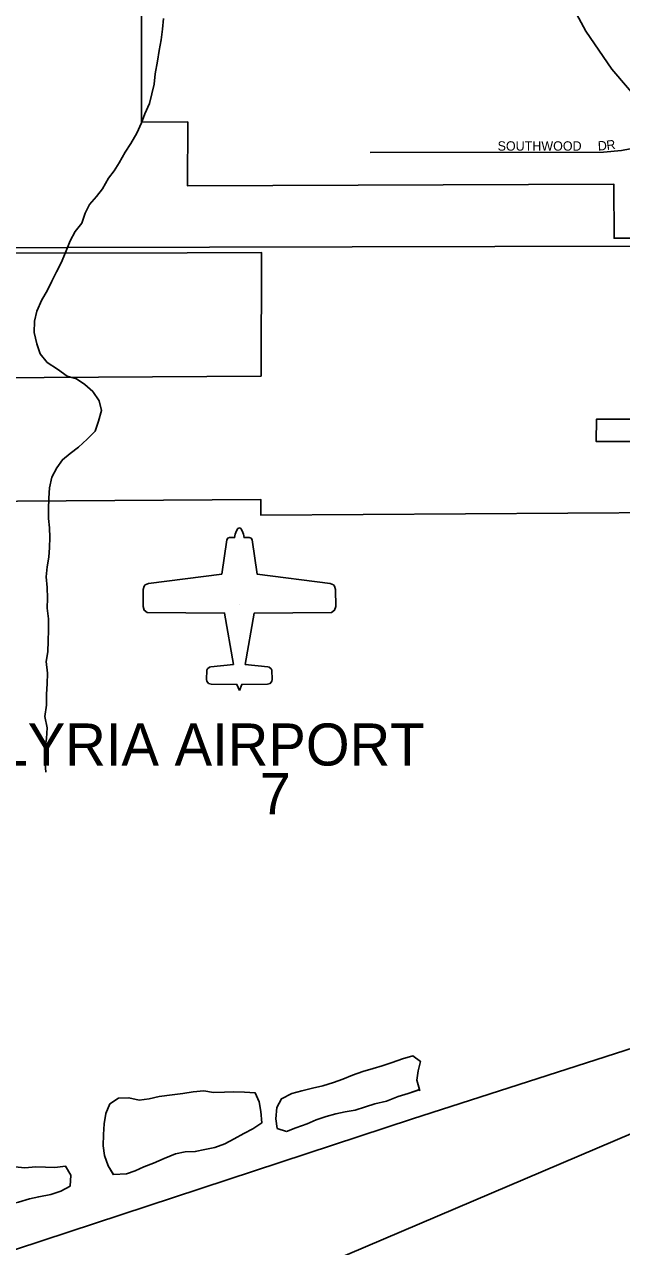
# Model space of a CAD drawing. Extents: x 1857828 to 2277390, y 930619 to 1324581.
# Drawn here: x 2077646 to 2080841, y 1210395 to 1216929 of the extents above; entities that cross this region are included whole.
import ezdxf

# ---------------------------------------------------------------- set-up
doc = ezdxf.new("R2010")
doc.units = 0
for name, color, linetype in [('GM_X_Airport_Class_3', 7, 'Continuous'), ('GM_X_Airport_Location_Class_3', 7, 'Continuous'), ('GM_X_Airport_Text_Class_3', 7, 'Continuous'), ('GM_X_Corporation', 7, 'Continuous'), ('GM_X_County_Road', 7, 'Continuous'), ('GM_X_Minor_Lake', 7, 'Continuous'), ('GM_X_Minor_River', 7, 'Continuous'), ('GM_X_Section', 7, 'Continuous'), ('GM_X_Section_Text', 7, 'Continuous'), ('GM_X_Township_Subdivision', 7, 'Continuous'), ('GM_X_Township_Subdivision_Text', 7, 'Continuous'), ('GM_X_US_Route', 7, 'Continuous')]:
    doc.layers.add(name, color=color, linetype=linetype)

msp = doc.modelspace()

# ---------------------------------------------------------------- linework, layer by layer
at = {"layer": 'GM_X_Airport_Class_3'}
for points in [[(2078795.9, 1214237.5), (2078788.2, 1214234.2), (2078780, 1214222.1), (2078774, 1214204), (2078770.7, 1214185.7), (2078743.9, 1214185.8), (2078733.5, 1214182.2), (2078728, 1214174.3), (2078701.5, 1213990.2), (2078309.8, 1213940.1), (2078292.6, 1213932.5), (2078286.3, 1213925.4), (2078280.9, 1213907.3), (2078280.6, 1213816.5), (2078286.9, 1213797), (2078303.5, 1213784.9), (2078716.4, 1213782.2), (2078764.4, 1213507.8), (2078642.9, 1213494.1), (2078636, 1213492.2), (2078625, 1213483.1), (2078621.9, 1213476.6), (2078620.7, 1213426.2), (2078621.9, 1213418.5), (2078630.9, 1213406.1), (2078645.5, 1213401.3), (2078783.1, 1213400.9), (2078795.9, 1213368.8)], [(2078795.9, 1213368.8), (2078808.7, 1213400.9), (2078946.3, 1213401.3), (2078960.9, 1213406.1), (2078969.9, 1213418.5), (2078971.1, 1213426.2), (2078969.9, 1213476.6), (2078966.8, 1213483.1), (2078955.8, 1213492.2), (2078948.9, 1213494.1), (2078827.4, 1213507.8), (2078875.4, 1213782.2), (2079288.3, 1213784.9), (2079304.9, 1213797), (2079311.2, 1213816.5), (2079310.9, 1213907.3), (2079305.5, 1213925.4), (2079299.2, 1213932.5), (2079282, 1213940.1), (2078890.3, 1213990.2), (2078863.8, 1214174.3), (2078858.3, 1214182.2), (2078848, 1214185.8), (2078821.1, 1214185.7), (2078817.8, 1214204), (2078811.8, 1214222.1), (2078803.6, 1214234.2), (2078795.9, 1214237.5)]]:
    msp.add_lwpolyline(points, dxfattribs=at)
at = {"layer": 'GM_X_Airport_Location_Class_3'}
msp.add_line((2078795.9, 1213827.2), (2078795.9, 1213827.2), dxfattribs=at)
at = {"layer": 'GM_X_Corporation'}
for points in [[(2078272.2, 1217857.5), (2078272.2, 1216406.7), (2078519.9, 1216407.6), (2078518, 1216066.1), (2080799.4, 1216074.4), (2080801.1, 1215785.4), (2081069.2, 1215786.8)], [(2076298.8, 1215032.7), (2078912.2, 1215049.3), (2078913.5, 1215709.7), (2078516, 1215707.1), (2075296.1, 1215705)], [(2081058.7, 1214818.7), (2080706.5, 1214817.7), (2080705.1, 1214698.5), (2081053.7, 1214699.4)], [(2081100.6, 1214319.6), (2078910.7, 1214305.6), (2078910.9, 1214388.9), (2076565.7, 1214373.3)]]:
    msp.add_lwpolyline(points, dxfattribs=at)
at = {"layer": 'GM_X_County_Road'}
for points in [[(2084481.4, 1213642.1), (2084249.4, 1213874.3), (2084213, 1213908.4), (2084181.9, 1213938), (2084150, 1213963.7), (2084103.8, 1213997.9), (2084049, 1214032.5), (2083824.5, 1214148.2), (2082699.2, 1214730.9), (2082586.9, 1214795.9), (2082546.1, 1214823.7), (2082500.7, 1214856.2), (2082438.5, 1214905.4), (2082371.7, 1214977.8), (2082055.3, 1215322), (2081693.4, 1215722.8), (2081081.5, 1216369.5), (2080916.1, 1216542.2), (2080871.6, 1216592.1), (2080789.2, 1216690.2), (2080649.8, 1216892.8), (2080547.6, 1217082.7)], [(2073594.6, 1207932.1), (2076220, 1209011.3), (2080999.8, 1211044.3), (2081275, 1211117.7), (2081474.9, 1211179.1), (2082358.5, 1211451.5), (2082456.5, 1211486.3), (2082532.4, 1211514.8), (2082604.4, 1211541.4), (2082696.3, 1211576.1), (2082794.2, 1211618.8), (2082898, 1211665.6), (2082987.9, 1211714.3), (2083091.7, 1211771.2), (2083161.6, 1211809.7), (2083191.6, 1211824), (2083235.5, 1211842.3), (2083439.5, 1211899.7), (2084071.3, 1212080.3), (2085602.9, 1212500.2)]]:
    msp.add_lwpolyline(points, dxfattribs=at)
at = {"layer": 'GM_X_Minor_Lake'}
for points in [[(2079759.4, 1211234.2), (2079744.8, 1211284.2), (2079752.6, 1211334.5), (2079764.3, 1211384.8), (2079724.1, 1211414.7), (2079668, 1211398.3), (2079613.9, 1211379.9), (2079559.9, 1211361.5), (2079511.8, 1211347.1), (2079455.8, 1211330.7), (2079401.7, 1211312.3), (2079349.7, 1211289.9), (2079299.7, 1211271.5), (2079241.6, 1211255), (2079187.5, 1211242.7), (2079129.4, 1211228.2), (2079077.4, 1211213.9), (2079021.4, 1211185.4), (2078995.5, 1211139), (2078991.9, 1211078.7), (2078998.2, 1211026.5), (2079048.4, 1211010.8)], [(2079761.2, 1211228.1), (2079744.8, 1211284.2), (2079752.6, 1211334.5), (2079764.3, 1211384.8), (2079724.1, 1211414.7), (2079668, 1211398.3), (2079613.9, 1211379.9), (2079559.9, 1211361.5), (2079511.8, 1211347.1), (2079455.8, 1211330.7), (2079401.7, 1211312.3), (2079349.7, 1211289.9), (2079299.7, 1211271.5), (2079241.6, 1211255), (2079187.5, 1211242.7), (2079129.4, 1211228.2), (2079077.4, 1211213.9), (2079021.4, 1211185.4), (2078995.5, 1211139), (2078991.9, 1211078.7), (2078998.2, 1211026.5), (2079048.4, 1211010.8)], [(2078764.5, 1211222), (2078716.3, 1211219.7), (2078658.2, 1211219.3), (2078606, 1211227.1), (2078547.9, 1211222.7), (2078493.8, 1211214.3), (2078435.6, 1211205.9), (2078367.5, 1211197.5), (2078313.4, 1211185.1), (2078259.3, 1211178.7), (2078205.1, 1211190.4), (2078148.9, 1211188.1), (2078103, 1211157.7), (2078081.2, 1211107.3), (2078073.5, 1211051), (2078069.8, 1210994.7), (2078068.1, 1210934.4), (2078074.4, 1210882.2), (2078094.8, 1210826.1), (2078121.9, 1210780.2)], [(2078764.5, 1211222), (2078716.3, 1211219.7), (2078658.2, 1211219.3), (2078606, 1211227.1), (2078547.9, 1211222.7), (2078493.8, 1211214.3), (2078435.6, 1211205.9), (2078367.5, 1211197.5), (2078313.4, 1211185.1), (2078259.3, 1211178.7), (2078205.1, 1211190.4), (2078148.9, 1211188.1), (2078103, 1211157.7), (2078081.2, 1211107.3), (2078073.5, 1211051), (2078069.8, 1210994.7), (2078068.1, 1210934.4), (2078074.4, 1210882.2), (2078094.8, 1210826.1), (2078123.1, 1210778.1)], [(2078121.9, 1210780.2), (2078191.3, 1210784.5), (2078239.3, 1210800.9), (2078285.3, 1210821.3), (2078337.4, 1210841.7), (2078393.4, 1210866.1), (2078453.4, 1210890.6), (2078505.5, 1210901), (2078559.6, 1210903.3), (2078611.7, 1210913.7), (2078663.8, 1210924), (2078717.8, 1210944.4), (2078767.8, 1210970.9), (2078819.8, 1210999.3), (2078867.8, 1211023.7), (2078915.8, 1211056.2), (2078911.4, 1211116.4), (2078901.1, 1211168.6), (2078880.8, 1211216.7), (2078822.6, 1211220.3), (2078764.5, 1211222)], [(2078121.9, 1210780.2), (2078191.3, 1210784.5), (2078239.3, 1210800.9), (2078285.3, 1210821.3), (2078337.4, 1210841.7), (2078393.4, 1210866.1), (2078453.4, 1210890.6), (2078505.5, 1210901), (2078559.6, 1210903.3), (2078611.7, 1210913.7), (2078663.8, 1210924), (2078717.8, 1210944.4), (2078767.8, 1210970.9), (2078819.8, 1210999.3), (2078867.8, 1211023.7), (2078915.8, 1211056.2), (2078911.4, 1211116.4), (2078901.1, 1211168.6), (2078880.8, 1211216.7), (2078822.6, 1211220.3), (2078764.5, 1211222)], [(2079048.4, 1211010.8), (2079098.4, 1211029.1), (2079158.5, 1211051.6), (2079206.5, 1211072), (2079260.5, 1211090.4), (2079312.6, 1211104.8), (2079362.7, 1211115.1), (2079414.8, 1211123.5), (2079470.8, 1211141.9), (2079520.9, 1211158.3), (2079583, 1211172.8), (2079645, 1211197.2), (2079699.1, 1211213.6), (2079759.4, 1211234.2)], [(2079048.4, 1211010.8), (2079098.4, 1211029.1), (2079158.5, 1211051.6), (2079206.5, 1211072), (2079260.5, 1211090.4), (2079312.6, 1211104.8), (2079362.7, 1211115.1), (2079414.8, 1211123.5), (2079470.8, 1211141.9), (2079520.9, 1211158.3), (2079583, 1211172.8), (2079645, 1211197.2), (2079699.1, 1211213.6), (2079753.1, 1211232.1)], [(2077707.7, 1210821.8), (2077647.6, 1210815.4), (2077595.4, 1210821.1), (2077545.3, 1210820.8), (2077495.1, 1210820.5), (2077439, 1210820.1), (2077403.1, 1210783.7), (2077437.4, 1210735.7), (2077483.8, 1210689.8), (2077562.4, 1210620)], [(2077562.4, 1210620), (2077614.5, 1210632.3), (2077672.6, 1210650.8), (2077722.6, 1210661.1), (2077786.8, 1210673.6), (2077840.8, 1210692), (2077890.8, 1210718.4), (2077894.5, 1210776.7), (2077866.1, 1210824.7), (2077808, 1210818.3), (2077757.9, 1210820.1), (2077707.7, 1210821.8)]]:
    msp.add_lwpolyline(points, dxfattribs=at)
at = {"layer": 'GM_X_Minor_River'}
msp.add_lwpolyline([(2077760.3, 1212931.7), (2077756, 1212997.9), (2077755.7, 1213054.2), (2077763.4, 1213110.5), (2077767.1, 1213168.8), (2077754.7, 1213229), (2077764.4, 1213289.3), (2077764.1, 1213347.6), (2077767.8, 1213403.9), (2077769.5, 1213460.1), (2077763.1, 1213522.4), (2077770.9, 1213574.7), (2077772.6, 1213633), (2077774.2, 1213691.2), (2077773.9, 1213751.5), (2077767.6, 1213807.7), (2077769.3, 1213862), (2077767, 1213918.2), (2077762.7, 1213976.5), (2077768.4, 1214028.8), (2077776.1, 1214081), (2077779.8, 1214133.3), (2077781.6, 1214185.6), (2077779.3, 1214237.8), (2077775, 1214288), (2077774.7, 1214338.2), (2077776.4, 1214396.5), (2077780.1, 1214450.8), (2077791.8, 1214509.1), (2077819.6, 1214557.5), (2077849.5, 1214601.9), (2077891.4, 1214634.3), (2077935.4, 1214668.7), (2077981.3, 1214711.2), (2078025.1, 1214753.6), (2078042.9, 1214808), (2078058.6, 1214864.3), (2078046.3, 1214916.5), (2078011.9, 1214966.5), (2077969.6, 1215004.4), (2077925.3, 1215034.3), (2077875.1, 1215048.1), (2077822.8, 1215085.9), (2077768.4, 1215121.8), (2077730.1, 1215167.8), (2077711.7, 1215221.9), (2077697.4, 1215282.1), (2077699, 1215342.4), (2077712.8, 1215396.7), (2077738.5, 1215457.1), (2077768.3, 1215505.5), (2077792.1, 1215555.9), (2077817.9, 1215606.3), (2077841.7, 1215654.7), (2077865.5, 1215709.1), (2077891.2, 1215771.5), (2077917, 1215821.9), (2077952.9, 1215866.3), (2077970.6, 1215920.7), (2077994.4, 1215967), (2078032.3, 1216009.5), (2078064.2, 1216049.8), (2078096, 1216106.3), (2078125.8, 1216146.7), (2078153.7, 1216189), (2078185.5, 1216245.5), (2078215.3, 1216291.9), (2078247.1, 1216348.3), (2078272.8, 1216402.7), (2078290.6, 1216451.1), (2078314.4, 1216505.5), (2078328.1, 1216557.8), (2078339.9, 1216610.1), (2078345.6, 1216664.4), (2078357.3, 1216732.8), (2078367, 1216789.1), (2078376.7, 1216847.4), (2078384.4, 1216903.7), (2078390.1, 1216960)], dxfattribs=at)
at = {"layer": 'GM_X_Section'}
for points in [[(2079131.4, 1221341.6), (2081434.9, 1221340.3), (2081735.9, 1221339.4), (2081688.8, 1215745.2), (2076344.3, 1215732.7), (2076410.5, 1221338.4), (2078502.2, 1221340.9)], [(2076344.3, 1215732.7), (2081688.8, 1215745.2), (2081611.5, 1210047.1), (2076246.6, 1210012.2)]]:
    msp.add_lwpolyline(points, close=True, dxfattribs=at)
at = {"layer": 'GM_X_Township_Subdivision'}
msp.add_lwpolyline([(2081081.5, 1216369.5), (2080990.7, 1216285.9), (2080938, 1216273.2), (2080887.1, 1216264.1), (2080839.8, 1216255), (2080743.5, 1216245.9), (2079495.1, 1216244.1)], dxfattribs=at)
at = {"layer": 'GM_X_US_Route'}
msp.add_lwpolyline([(2073483.9, 1208952.2), (2073498.1, 1208959.3), (2073590.4, 1208999.9), (2074374.8, 1209322.4), (2074479.3, 1209360.1), (2075170.3, 1209609.3), (2076226, 1209942.8), (2077455.5, 1210333.7), (2079722.9, 1211077.9), (2081013.7, 1211494.1), (2081116, 1211525.8)], dxfattribs=at)

# ---------------------------------------------------------------- texts
at = {"layer": 'GM_X_Airport_Text_Class_3'}
msp.add_text('ELYRIA AIRPORT', height=225, rotation=0.00001, dxfattribs=at).set_placement((2077295.5, 1212966.7))
at = {"layer": 'GM_X_Section_Text'}
msp.add_text('7', height=221, rotation=0.00001, dxfattribs=at).set_placement((2078905.9, 1212705.8))
at = {"layer": 'GM_X_Township_Subdivision_Text'}
for s, rotation, p in [('SOUTHWOOD', 0.00001, (2080177.5, 1216254.2)), ('D', 3.41138, (2080715.1, 1216254.2)), ('R', 7.58883, (2080762.9, 1216257.2))]:
    msp.add_text(s, height=50, rotation=rotation, dxfattribs=at).set_placement(p)

doc.saveas('drawing.dxf')
